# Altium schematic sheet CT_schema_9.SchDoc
size 274 x 160 mm
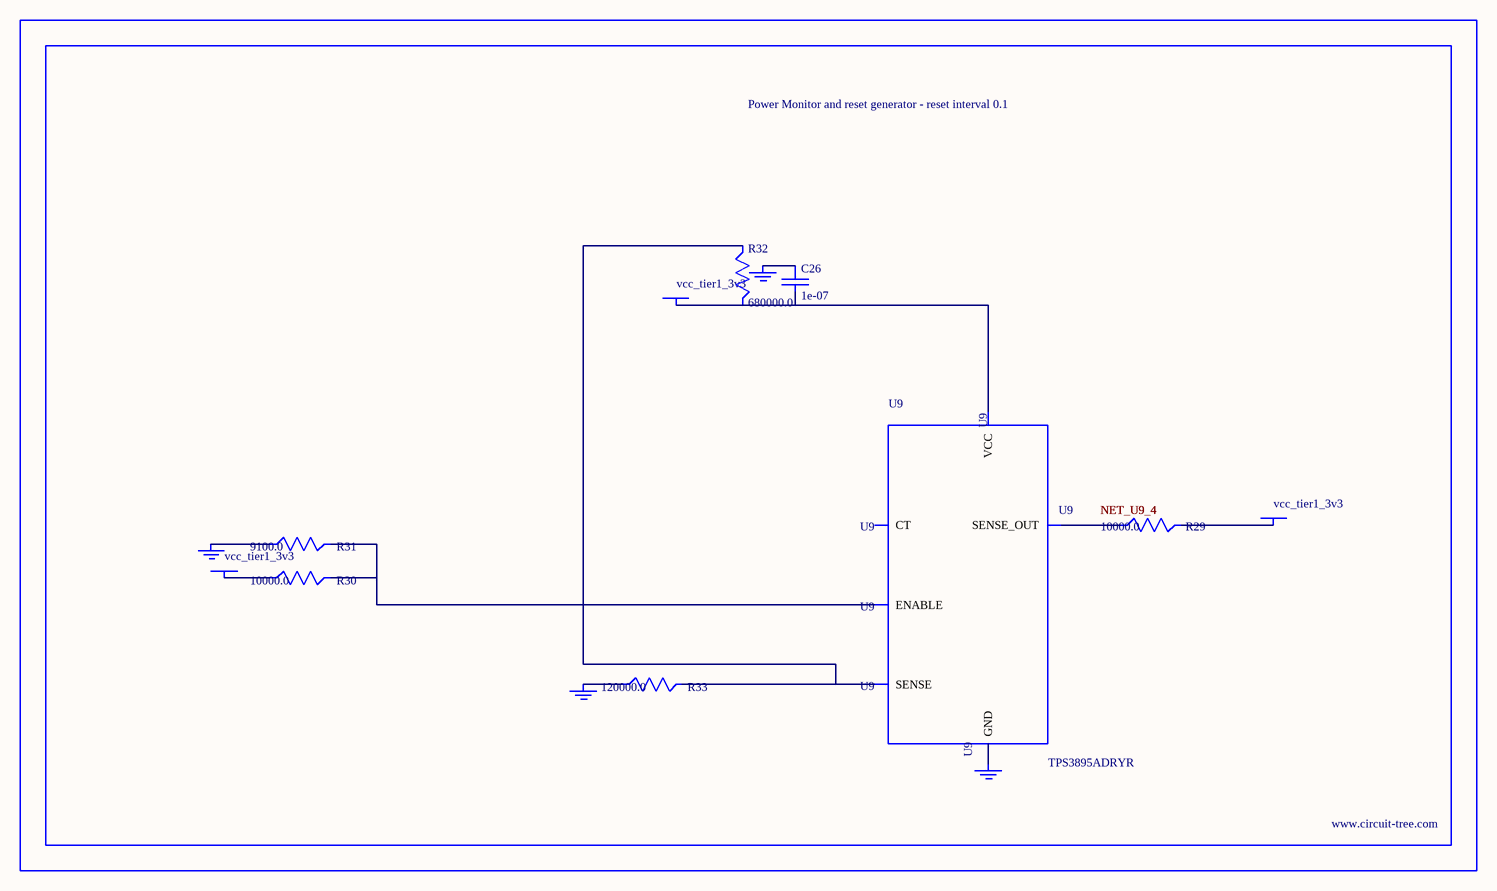
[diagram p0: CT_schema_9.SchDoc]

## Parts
BORDER8  (no value)
C26  1e-07  [C0402]
GND_INSTANCE_8_0  (no value)
GND_INSTANCE_8_1  (no value)
GND_INSTANCE_8_2  (no value)
GND_INSTANCE_8_3  (no value)
POWER_INSTANCE_8_0  vcc_tier1_3v3
POWER_INSTANCE_8_1  vcc_tier1_3v3
POWER_INSTANCE_8_2  vcc_tier1_3v3
R29  10000.0  [R0603]
R30  10000.0  [R0603]
R31  9100.0  [R0603]
R32  680000.0  [R0603]
R33  120000.0  [R0603]
U9  TPS3895ADRYR  [SON-6]

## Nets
NetC26_1: C26.1 GND_INSTANCE_8_2.0(GND)
NetC26_2: C26.2 POWER_INSTANCE_8_2.0(PWR) R32.2 U9.6(VCC)
NetGND_INSTANCE_8_0_0: GND_INSTANCE_8_0.0(GND) R31.1
NetGND_INSTANCE_8_1_0: GND_INSTANCE_8_1.0(GND) R33.1
NetGND_INSTANCE_8_3_0: GND_INSTANCE_8_3.0(GND) U9.2(GND)
NetPOWER_INSTANCE_8_0_0: POWER_INSTANCE_8_0.0(PWR) R30.1
NetPOWER_INSTANCE_8_1_0: POWER_INSTANCE_8_1.0(PWR) R29.2
NetR29_1: R29.1 U9.4(SENSE_OUT)
NetR30_2: R30.2 R31.2 U9.1(ENABLE)
NetR32_1: R32.1 R33.2 U9.3(SENSE)

Not connected (* = marked no-connect by the designer): U9 5(CT)

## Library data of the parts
BORDER8 = BORDER_PAGE8
C26 = C0402C104K3RACTU
GND_INSTANCE_8_0-GND_INSTANCE_8_3 = GND
POWER_INSTANCE_8_0-POWER_INSTANCE_8_2 = PWR
R29 R30 = RC0603JR-0710KL
R31 = RC0603JR-079K1L
R32 = RC0603JR-07680KL
R33 = RC0603JR-07120KL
